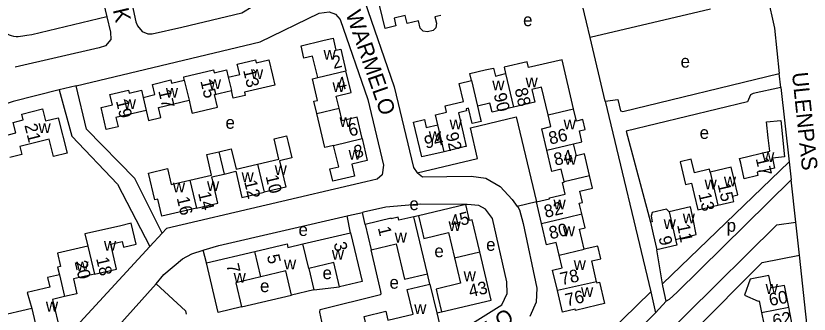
# Model space of a CAD drawing. Extents: x 157646 to 159241, y 379213 to 381217.
# Drawn here: x 158162.1 to 158413, y 380564.5 to 380658.9 of the extents above; entities that cross this region are included whole.
import ezdxf

# ---------------------------------------------------------------- set-up
doc = ezdxf.new("R2010")
doc.units = 0
for name, color, linetype in [('BLT_Basislijn', 7, 'Continuous'), ('BLT_Bebouwing', 7, 'Continuous'), ('BLT_Centroide', 7, 'Continuous'), ('BLT_Huisnummer', 7, 'Continuous'), ('BLT_Onderverdeling_panden', 7, 'Continuous'), ('BLT_Straatnaam', 7, 'Continuous')]:
    doc.layers.add(name, color=color, linetype=linetype)

msp = doc.modelspace()

# ---------------------------------------------------------------- linework, layer by layer
at = {"layer": 'BLT_Basislijn'}
for p, q in [((158348.47, 380631.87), (158343.74, 380651.99)), ((158403.98, 380636.16), (158403.54, 380640.58)), ((158181.13, 380636.75), (158175.77, 380635.43)), ((158403.98, 380636.16), (158406.62, 380612.71)), ((158348.47, 380631.87), (158362.89, 380571.52)), ((158366.63, 380574.09), (158406.62, 380612.71)), ((158406.62, 380612.71), (158407.25, 380607.02)), ((158408.77, 380593.57), (158407.25, 380607.02)), ((158326.75, 380599.99), (158320.69, 380598.56)), ((158320.69, 380598.56), (158320.81, 380598.41)), ((158267.98, 380590.24), (158266.84, 380595.55)), ((158272.54, 380592.88), (158271.76, 380596.69)), ((158289.48, 380595.61), (158288, 380595.31)), ((158409.95, 380583.17), (158408.77, 380593.57)), ((158204.53, 380585.91), (158208.41, 380590.08)), ((158222.4, 380580.73), (158221.37, 380584.71)), ((158366.63, 380574.09), (158364.79, 380584.88)), ((158293.05, 380573.96), (158292.25, 380577.28)), ((158256.33, 380572.18), (158264.49, 380573.14)), ((158366.74, 380573.46), (158366.63, 380574.09)), ((158367.81, 380568.55), (158366.74, 380573.46)), ((158233.44, 380566.78), (158249.28, 380570.51)), ((158337.01, 380546.43), (158362.89, 380571.52)), ((158362.89, 380571.52), (158364.39, 380564.93)), ((158364.39, 380564.93), (158367.81, 380568.55)), ((158295.19, 380564.9), (158296.75, 380565.24)), ((158341.49, 380542.56), (158364.39, 380564.93))]:
    msp.add_line(p, q, dxfattribs=at)
for points in [[(158190.58, 380711.16), (158188.15, 380710.58), (158188.12, 380710.02), (158194.21, 380683.94), (158200.09, 380656.96), (158200.56, 380655.7), (158202.03, 380653.89), (158203.87, 380653.16), (158205.21, 380653.16), (158214.6, 380655.3), (158233.53, 380659.84), (158237.07, 380661.95)], [(158181.94, 380696.44), (158190.9, 380658.59)], [(158334.69, 380690.66), (158334.32, 380690.56), (158306.8, 380683.88), (158298.28, 380681.17), (158288.74, 380677.5), (158275.69, 380670.09), (158272.57, 380667.25), (158272.32, 380663.58), (158281.74, 380636.45), (158287.85, 380610.84), (158289.05, 380609.24)], [(158399.81, 380664.94), (158401.98, 380654.96), (158403.54, 380640.58)], [(158190.9, 380658.59), (158192.05, 380653.74), (158192.11, 380651.39), (158190.49, 380649.39), (158188.49, 380648.79), (158161.85, 380642.64)], [(158190.9, 380658.59), (158167.11, 380652.87), (158165.54, 380652.6), (158164.27, 380652.44)], [(158181.13, 380636.75), (158239.35, 380650.66), (158258.03, 380659.68), (158261.21, 380660.16), (158263.18, 380659.36), (158264.65, 380657.71), (158273.4, 380632.41), (158278.36, 380611.6), (158277.92, 380608.61), (158276.33, 380607.24), (158272.8, 380606.31), (158209.74, 380591.54), (158208.41, 380590.08)], [(158164.27, 380652.44), (158163.58, 380652.3), (158162.87, 380652.24), (158162.17, 380652.26), (158161.47, 380652.35), (158160.78, 380652.53), (158160.12, 380652.78), (158159.49, 380653.11), (158158.91, 380653.5), (158158.43, 380653.9)], [(158348.47, 380631.87), (158352.47, 380632.4), (158353.36, 380628.8), (158354.1, 380628.64), (158403.54, 380640.58)], [(158175.77, 380635.43), (158161.21, 380631.77), (158156.75, 380630.24), (158148.79, 380625.89), (158142.68, 380620.8), (158139.58, 380617.09), (158122.17, 380593.19), (158088.91, 380548.79), (158087.38, 380546.5), (158085.15, 380541.88), (158083.98, 380537.65), (158083.7, 380528.68), (158092.89, 380456.03), (158094.64, 380453.46), (158097.98, 380452.14), (158149.23, 380463.59), (158151.12, 380464.15), (158152.81, 380465.76), (158153.39, 380468.79), (158147.46, 380517.85), (158147.9, 380522.87), (158148.44, 380524.46), (158150.49, 380527.42), (158204.53, 380585.91)], [(158175.77, 380635.43), (158179.77, 380620.83), (158194.3, 380605.62), (158204.53, 380585.91)], [(158208.41, 380590.08), (158199.74, 380607.43), (158184.4, 380622.99), (158181.13, 380636.75)], [(158403.98, 380636.16), (158395.24, 380634.32), (158394.44, 380633.84), (158393.52, 380631.63), (158355.16, 380622.42), (158362.77, 380593.59)], [(158289.05, 380609.24), (158308.12, 380613.75), (158305.84, 380623.48), (158320.32, 380626.87), (158326.75, 380599.99)], [(158289.05, 380609.24), (158289.12, 380609.15), (158290.71, 380607.93), (158306.08, 380608.13), (158310.74, 380607.49)], [(158310.74, 380607.49), (158315.24, 380604.89), (158319.09, 380600.78), (158320.69, 380598.56)], [(158407.25, 380607.02), (158371.23, 380571.45), (158368.76, 380569.11), (158367.81, 380568.55)], [(158245.14, 380520.77), (158250.62, 380526.37), (158254.8, 380529.71), (158285.96, 380548.74), (158315.78, 380567.4), (158317.48, 380571.03), (158317.34, 380574.69), (158312.89, 380594.77), (158310.67, 380597.7), (158308.56, 380598.87), (158304.79, 380599.21), (158304.38, 380599.21)], [(158304.38, 380599.21), (158290.07, 380599.3), (158279.1, 380598.35), (158272.04, 380596.75), (158271.76, 380596.69)], [(158320.81, 380598.41), (158321.35, 380597.47), (158322.52, 380593.15), (158326.84, 380572.7), (158326.63, 380568.3), (158324.66, 380563.71)], [(158221.37, 380584.71), (158221.71, 380584.82), (158226.3, 380586.21), (158266.84, 380595.55)], [(158266.84, 380595.55), (158267.29, 380595.66), (158271.76, 380596.69)], [(158345.58, 380536.24), (158402.72, 380592.79), (158408.77, 380593.57)], [(158206.48, 380574.08), (158208.92, 380577.03), (158214.82, 380582.04), (158217.71, 380583.55), (158221.37, 380584.71)], [(158245.37, 380554.46), (158246.58, 380554.68), (158259.79, 380557.7), (158258.19, 380565.13), (158258.38, 380565.93), (158277.39, 380570.67), (158277.63, 380570.93), (158277.57, 380571.67), (158274.44, 380584.86)], [(158354.88, 380525.33), (158358.68, 380528.77), (158356.65, 380540.46), (158356.75, 380541.31), (158378.2, 380545.77), (158375.99, 380558.59), (158398.1, 380580.88), (158409.95, 380583.17)], [(158382, 380486.03), (158394.7, 380478.15), (158397.65, 380476.58), (158401, 380475.76), (158402.65, 380477.1), (158414.74, 380494.85), (158416.53, 380498.98), (158417.47, 380503.76), (158417.68, 380511.48), (158409.95, 380583.17)], [(158192.44, 380460.23), (158189.56, 380457.85), (158185.09, 380454.13), (158182.48, 380452.66), (158178.96, 380452.33), (158177.37, 380452.85), (158168.77, 380457.81), (158165.12, 380461.91), (158164.05, 380463.75), (158162.83, 380467.65), (158157.4, 380511.32), (158157.32, 380517.6), (158158.75, 380521.1), (158160.25, 380523.11), (158189.19, 380554.74), (158206.48, 380574.08)], [(158206.48, 380574.08), (158215.77, 380565.54), (158215.93, 380564.47)]]:
    msp.add_lwpolyline(points, dxfattribs=at)
at = {"layer": 'BLT_Bebouwing'}
for p, q in [((158381.76, 380660.92), (158343.74, 380651.99)), ((158304.38, 380599.21), (158289.48, 380595.61)), ((158328.34, 380593.22), (158326.75, 380599.99)), ((158292.25, 380577.28), (158288, 380595.31)), ((158272.54, 380592.88), (158274.44, 380584.86)), ((158252.9, 380586.69), (158267.98, 380590.24)), ((158222.4, 380580.73), (158237.66, 380584.33)), ((158254.73, 380578.95), (158256.33, 380572.18)), ((158293.05, 380573.96), (158295.19, 380564.9)), ((158256.33, 380572.18), (158249.28, 380570.51)), ((158177.51, 380570.05), (158173.74, 380569.18))]:
    msp.add_line(p, q, dxfattribs=at)
for points in [[(158343.74, 380651.99), (158342.6, 380656.85), (158339.99, 380667.96)], [(158285.27, 380659), (158281.7, 380658.16), (158282.29, 380655.66), (158278.88, 380654.86), (158276.31, 380665.8), (158283.28, 380667.44)], [(158296.55, 380658.98), (158294.66, 380658.54), (158295.13, 380656.52), (158294.9, 380655.12), (158294.05, 380654.22), (158292.32, 380653.81), (158290.93, 380654.04), (158289.99, 380654.92), (158289.43, 380657.31), (158285.86, 380656.47), (158285.27, 380659)], [(158257.57, 380639.32), (158255.97, 380646.11), (158253.23, 380645.47), (158252.3, 380649.42), (158259.22, 380651.05), (158262.41, 380651.8), (158263.32, 380647.95), (158264.89, 380648.32), (158266.51, 380641.43)], [(158229.25, 380639.44), (158232.9, 380640.3), (158232.13, 380643.6), (158237.93, 380644.97), (158238.15, 380644.01), (158242.1, 380644.94), (158243.24, 380640.08), (158243.97, 380636.98), (158234.37, 380634.72), (158234.62, 380633.65), (158230.88, 380632.77), (158230.29, 380635.27)], [(158338.49, 380629.41), (158334.83, 380644.99), (158324.26, 380642.51), (158323.84, 380644.3), (158316.5, 380642.58), (158316.97, 380640.57)], [(158215.36, 380638.55), (158215.22, 380639.54), (158224.61, 380641.75), (158224.82, 380640.83), (158228.71, 380641.75), (158229.25, 380639.44)], [(158264.34, 380629.61), (158263.43, 380633.48), (158268.13, 380634.59), (158266.51, 380641.43)], [(158306.19, 380638.36), (158305.67, 380640.59), (158310.54, 380641.73), (158313.2, 380642.36), (158313.8, 380639.83), (158316.97, 380640.57)], [(158202.38, 380633.06), (158206.07, 380633.93), (158205.3, 380637.19), (158211.14, 380638.57), (158211.37, 380637.61), (158215.36, 380638.55)], [(158257.31, 380627.95), (158256.38, 380631.87), (158257.48, 380632.13), (158255.87, 380638.95), (158257.57, 380639.32)], [(158295.58, 380624.39), (158294.83, 380627.59), (158298.32, 380628.41), (158297.85, 380630.4), (158303.66, 380631.76), (158302.32, 380637.45), (158306.19, 380638.36)], [(158203.35, 380628.95), (158193.76, 380626.69), (158194.45, 380623.78), (158190.72, 380622.9), (158189.07, 380629.88), (158192.64, 380630.72), (158191.88, 380633.95), (158197.74, 380635.33), (158197.96, 380634.38), (158201.85, 380635.3), (158202.38, 380633.06)], [(158330.43, 380627.56), (158328.37, 380636.31), (158325.27, 380635.58), (158326.21, 380631.54), (158319.46, 380629.95)], [(158216.88, 380632.15), (158217.47, 380629.64), (158217.85, 380628.03), (158225.88, 380629.93), (158224.92, 380634.01)], [(158224.92, 380634.01), (158230.29, 380635.27)], [(158203.35, 380628.95), (158204.09, 380625.8), (158207.96, 380626.71), (158207.21, 380629.87), (158216.88, 380632.15)], [(158308.08, 380630.33), (158308.98, 380626.59), (158309.26, 380625.42), (158306.43, 380624.76), (158305.28, 380629.68), (158304.5, 380629.49), (158304.66, 380628.82), (158302.05, 380628.21), (158303.58, 380621.71), (158304.56, 380617.54), (158304.29, 380617.48), (158297.52, 380615.89)], [(158319.46, 380629.95), (158312.72, 380628.36), (158312.04, 380631.26), (158308.08, 380630.33)], [(158158.51, 380620.92), (158162.07, 380621.82), (158161.24, 380625.12), (158164.43, 380625.92), (158163.97, 380627.78), (158170.56, 380629.43), (158171.52, 380625.6), (158175.5, 380626.6), (158178.31, 380615.45), (158173.99, 380614.37), (158172.61, 380619.86), (158163.4, 380617.54), (158164.03, 380615.02), (158160.23, 380614.07)], [(158262.61, 380617.89), (158259.85, 380617.17), (158257.31, 380627.95)], [(158271.6, 380620.01), (158270.01, 380626.8), (158265.27, 380625.68), (158264.34, 380629.61)], [(158338.46, 380618.36), (158341.13, 380618.99), (158340.32, 380622.45), (158342.19, 380622.89), (158341.44, 380626.06), (158339.39, 380625.58), (158338.49, 380629.41)], [(158297.52, 380615.89), (158290.48, 380614.23), (158287.88, 380625.24), (158291.33, 380626.05), (158291.92, 380623.53), (158295.58, 380624.39)], [(158330.03, 380616.38), (158328.44, 380623.14), (158331.31, 380623.81), (158330.43, 380627.56)], [(158400.07, 380620.32), (158399.54, 380625.3), (158404.01, 380625.77), (158405.23, 380614.21), (158401.38, 380613.8), (158401.99, 380610.68), (158396.57, 380609.38), (158396.8, 380608.39), (158392.46, 380607.35), (158391.33, 380612.21), (158390.97, 380613.73), (158400.52, 380616.02), (158400.07, 380620.32)], [(158238.53, 380611.91), (158245.32, 380613.51), (158243.81, 380619.94), (158247.74, 380620.86), (158248.23, 380618.79), (158249.38, 380613.92), (158245.49, 380613.01), (158247.45, 380604.69), (158240.61, 380603.08)], [(158271.6, 380620.01), (158273.24, 380613.09), (158268.36, 380611.94), (158269.25, 380608.15), (158262.37, 380606.53), (158261.45, 380610.45), (158264.21, 380611.11), (158262.61, 380617.89)], [(158343.56, 380608.34), (158341.96, 380615.17), (158339.36, 380614.56), (158338.46, 380618.36)], [(158217.12, 380606.88), (158224, 380608.5), (158222.47, 380614.98), (158226.34, 380615.89)], [(158226.34, 380615.89), (158230.21, 380616.81), (158231.74, 380610.31), (158238.53, 380611.91)], [(158335.47, 380606.44), (158334.56, 380610.32), (158331.62, 380609.63), (158330.03, 380616.38)], [(158381.65, 380609.44), (158381.45, 380610.34), (158376.73, 380609.23), (158375.72, 380613.52), (158372.21, 380612.69), (158373.91, 380605.54), (158375.78, 380605.97)], [(158219.21, 380598.02), (158208.29, 380595.45), (158207.01, 380600.91), (158206.03, 380600.68), (158204.05, 380609.12), (158210.03, 380610.53), (158211.22, 380605.49)], [(158384.09, 380598.96), (158389.12, 380600.13), (158388.72, 380601.87), (158390.38, 380602.25), (158389.24, 380607.12), (158388.35, 380610.99), (158381.65, 380609.44)], [(158219.21, 380598.02), (158226.01, 380599.62), (158224.06, 380607.89), (158228.01, 380608.82)], [(158228.01, 380608.82), (158231.65, 380609.68), (158233.59, 380601.43), (158240.61, 380603.08)], [(158341.08, 380596.22), (158340.29, 380599.56), (158341.29, 380599.8), (158340.45, 380603.36), (158344.51, 380604.32), (158343.56, 380608.34)], [(158211.22, 380605.49), (158217.12, 380606.88)], [(158335.81, 380602.42), (158334.94, 380606.09), (158335.52, 380606.22), (158335.47, 380606.44)], [(158375.78, 380605.97), (158376.62, 380602.36), (158377.75, 380597.49), (158384.09, 380598.96)], [(158326.75, 380599.99), (158330.9, 380600.96), (158330.83, 380601.25), (158335.81, 380602.42)], [(158308.81, 380584.16), (158306.42, 380594.33), (158305.56, 380594.13), (158304.38, 380599.21)], [(158368.73, 380596.82), (158367.91, 380597.72), (158363.32, 380596.65), (158362.98, 380595.51), (158363.39, 380593.74), (158362.77, 380593.59)], [(158370.74, 380588.16), (158377.29, 380589.68), (158376.29, 380594.58), (158375.51, 380598.4), (158368.73, 380596.82)], [(158288, 380595.31), (158283.25, 380594.19), (158283.02, 380595.2), (158280.82, 380594.68), (158280.78, 380594.82), (158272.54, 380592.88)], [(158289.48, 380595.61), (158290.62, 380590.74), (158291.17, 380588.45), (158298.97, 380590.29), (158300.86, 380582.28)], [(158341.84, 380585.01), (158340.36, 380591.33), (158342.13, 380591.75), (158341.08, 380596.22)], [(158187.02, 380577.16), (158193.93, 380578.75), (158192.11, 380586.68), (158195.71, 380587.51), (158196.12, 380585.7), (158200.12, 380586.61), (158198.59, 380593.24), (158194.85, 380592.38), (158183.97, 380589.88), (158184.87, 380585.95)], [(158333.88, 380583.14), (158332.94, 380587.17), (158329.92, 380586.46), (158328.34, 380593.22)], [(158362.77, 380593.59), (158363.66, 380589.76), (158364.79, 380584.88)], [(158267.98, 380590.24), (158271.62, 380574.82), (158264.49, 380573.14)], [(158370.74, 380588.16), (158371.16, 380586.36), (158364.79, 380584.88)], [(158184.87, 380585.95), (158175.31, 380583.75), (158176.27, 380579.57), (158175.33, 380579.35), (158175.92, 380576.97)], [(158237.66, 380584.33), (158247.87, 380586.74), (158248.15, 380585.57), (158252.9, 380586.69)], [(158274.44, 380584.86), (158282.38, 380586.73), (158285.01, 380575.57), (158292.25, 380577.28)], [(158345.77, 380574.68), (158344.21, 380581.33), (158347.12, 380582.01), (158346.19, 380585.97), (158341.84, 380585.01)], [(158296.75, 380565.24), (158312.39, 380568.94), (158308.81, 380584.16)], [(158333.39, 380571.97), (158331.87, 380578.43), (158334.83, 380579.12), (158333.88, 380583.14)], [(158233.44, 380566.78), (158226.1, 380565.04), (158222.4, 380580.73)], [(158264.49, 380573.14), (158262.67, 380580.83), (158254.73, 380578.95)], [(158300.86, 380582.28), (158302.75, 380574.27), (158295.04, 380572.45), (158295.6, 380570.11), (158296.75, 380565.24)], [(158249.28, 380570.51), (158247.47, 380578.17), (158239.55, 380576.3)], [(158175.92, 380576.97), (158172.15, 380576.1), (158172.87, 380573)], [(158187.02, 380577.16), (158180.32, 380575.62), (158181.39, 380570.94), (158177.51, 380570.05)], [(158239.55, 380576.3), (158231.63, 380574.43), (158233.44, 380566.78)], [(158406.56, 380566.72), (158405.24, 380573.58), (158401.05, 380572.77), (158400.28, 380576.75), (158394.34, 380575.61), (158392.55, 380570.48), (158396.86, 380568.64), (158397.2, 380568.71), (158397.91, 380565.06)], [(158172.87, 380573), (158165.71, 380571.36), (158167.16, 380566.23)], [(158279.73, 380562.58), (158287.75, 380564.47), (158285.91, 380572.27), (158293.05, 380573.96)], [(158345.77, 380574.68), (158345.84, 380574.39), (158346.68, 380574.59), (158348.26, 380567.85), (158346.04, 380567.33), (158339.11, 380565.7), (158339.02, 380566.08), (158334.99, 380565.14), (158333.39, 380571.97)], [(158173.74, 380569.18), (158176.09, 380558.98), (158169.19, 380557.39)], [(158167.16, 380566.23), (158156.24, 380563.72), (158157.58, 380557.89)], [(158266.08, 380554.12), (158274.05, 380556), (158272.21, 380563.77), (158279.07, 380565.39), (158279.73, 380562.58)], [(158397.91, 380565.06), (158398.61, 380561.41), (158394.14, 380560.55), (158395.09, 380555.64), (158395.5, 380553.5)], [(158403.65, 380555.07), (158402.88, 380559.08), (158407.85, 380560.04), (158406.56, 380566.72)], [(158295.19, 380564.9), (158296.47, 380559.49), (158291.75, 380558.38), (158292.03, 380557.2), (158281.8, 380554.78)]]:
    msp.add_lwpolyline(points, dxfattribs=at)
at = {"layer": 'BLT_Onderverdeling_panden'}
for p, q in [((158257.57, 380639.32), (158266.51, 380641.43)), ((158316.97, 380640.57), (158319.46, 380629.95)), ((158215.36, 380638.55), (158216.88, 380632.15)), ((158229.25, 380639.44), (158230.29, 380635.27)), ((158306.19, 380638.36), (158308.08, 380630.33)), ((158202.38, 380633.06), (158203.35, 380628.95)), ((158257.31, 380627.95), (158264.34, 380629.61)), ((158330.43, 380627.56), (158338.49, 380629.41)), ((158297.52, 380615.89), (158295.58, 380624.39)), ((158262.61, 380617.89), (158271.6, 380620.01)), ((158330.03, 380616.38), (158338.46, 380618.36)), ((158226.34, 380615.89), (158228.01, 380608.82)), ((158238.53, 380611.91), (158240.61, 380603.08)), ((158335.47, 380606.44), (158343.56, 380608.34)), ((158381.65, 380609.44), (158384.09, 380598.96)), ((158217.12, 380606.88), (158219.21, 380598.02)), ((158328.34, 380593.22), (158336.73, 380595.19)), ((158336.73, 380595.19), (158341.08, 380596.22)), ((158368.73, 380596.82), (158370.74, 380588.16)), ((158184.87, 380585.95), (158187.02, 380577.16)), ((158254.73, 380578.95), (158252.9, 380586.69)), ((158239.55, 380576.3), (158237.66, 380584.33)), ((158300.86, 380582.28), (158308.81, 380584.16)), ((158333.88, 380583.14), (158341.84, 380585.01)), ((158175.92, 380576.97), (158177.51, 380570.05)), ((158345.77, 380574.68), (158333.39, 380571.97)), ((158167.16, 380566.23), (158169.19, 380557.39)), ((158397.91, 380565.06), (158406.56, 380566.72))]:
    msp.add_line(p, q, dxfattribs=at)

# ---------------------------------------------------------------- texts
at = {"layer": 'BLT_Centroide'}
for s, p in [('e', (158322.52, 380655.6)), ('w', (158259.41, 380645)), ('e', (158372.33, 380642.49)), ('w', (158236.46, 380638.88)), ('w', (158223.13, 380635.69)), ('w', (158262.25, 380634.78)), ('w', (158312.77, 380635.31)), ('w', (158323.3, 380636.28)), ('w', (158209.54, 380633)), ('w', (158196.23, 380629.34)), ('e', (158228.41, 380623.14)), ('w', (158264.45, 380623.73)), ('w', (158299.27, 380622.99)), ('w', (158335.34, 380622.91)), ('w', (158169.27, 380621.75)), ('e', (158378.35, 380619.93)), ('w', (158292.7, 380619.23)), ('w', (158267.34, 380613.34)), ('w', (158398.09, 380612.59)), ('w', (158335.62, 380611.73)), ('w', (158243.95, 380608.53)), ('w', (158233.48, 380606.31)), ('w', (158386.02, 380604.92)), ('w', (158211.76, 380603)), ('w', (158222.56, 380603.48)), ('w', (158379.91, 380603.98)), ('e', (158286.57, 380597.41)), ('w', (158332.14, 380597.6)), ('w', (158373, 380593.25)), ('w', (158298.95, 380590.75)), ('w', (158366.97, 380591.44)), ('p', (158386.89, 380590.56)), ('e', (158251.5, 380589.22)), ('w', (158281.91, 380587.16)), ('w', (158335.07, 380589.16)), ('e', (158310.83, 380584.54)), ('w', (158189.97, 380584.55)), ('e', (158294.47, 380582.49)), ('w', (158262.04, 380581.69)), ('w', (158181.23, 380578)), ('w', (158246.9, 380578.62)), ('w', (158338.52, 380578.5)), ('e', (158259.1, 380575.55)), ('w', (158303.72, 380574.92)), ('w', (158230.97, 380574.47)), ('e', (158280.27, 380572.55)), ('e', (158239.33, 380571.46)), ('w', (158340.83, 380569.91)), ('w', (158399.23, 380570.91)), ('w', (158171.61, 380565.33)), ('w', (158288.09, 380564.53))]:
    msp.add_text(s, height=4, dxfattribs=at).set_placement(p)
at = {"layer": 'BLT_Huisnummer'}
for s, rotation, p in [('2', 13.2613, (158262.63, 380642.05)), ('13', 283.256, (158233.95, 380641.67)), ('15', 283.2651, (158220.43, 380638.27)), ('4', 13.2613, (158264.19, 380635.18)), ('17', 283.264, (158207.13, 380635.12)), ('88', 283.2193, (158319.82, 380635.65)), ('90', 283.224, (158313.18, 380634.03)), ('19', 283.2613, (158193.73, 380631.97)), ('21', 284.1097, (158164.78, 380624.26)), ('6', 13.2613, (158267.77, 380620.64)), ('86', 13.2283, (158331.1, 380618.11)), ('94', 13.2875, (158291.77, 380616.8)), ('92', 283.2243, (158297.98, 380621.57)), ('8', 13.2613, (158269.5, 380613.76)), ('84', 13.2143, (158332.73, 380611.4)), ('17', 283.1552, (158396.05, 380613.72)), ('10', 283.262, (158241.07, 380608.11)), ('12', 283.261, (158234.27, 380606.47)), ('15', 283.0831, (158383.99, 380605.58)), ('14', 283.2602, (158219.71, 380602.8)), ('13', 283.0831, (158377.94, 380602.53)), ('16', 283.2666, (158212.94, 380601.24)), ('82', 13.2182, (158329.66, 380594.92)), ('45', 13.2838, (158300.03, 380591.77)), ('80', 13.2297, (158331.2, 380588.15)), ('11', 281.5009, (158371.2, 380592.7)), ('1', 283.2823, (158276.55, 380591.81)), ('9', 283.0831, (158365.32, 380588.76)), ('3', 283.2816, (158262.56, 380586.91)), ('5', 283.286, (158241.45, 380582.96)), ('20', 282.9454, (158180.67, 380581.04)), ('18', 282.9404, (158187.46, 380582.11)), ('7', 283.2839, (158228.62, 380580.03)), ('78', 13.2053, (158334.74, 380573.59)), ('43', 13.2858, (158305.8, 380569.79)), ('76', 13.2254, (158336.35, 380566.93)), ('60', 10.8928, (158400.64, 380567.02)), ('62', 10.8928, (158401.8, 380560.36))]:
    msp.add_text(s, height=4, rotation=rotation, dxfattribs=at).set_placement(p)
at = {"layer": 'BLT_Straatnaam'}
for s, rotation, p in [('ROOSWIJCK', 283.1446, (158184.55, 380695.84)), ('WARMELO', 289.08, (158266.33, 380659.6)), ('ULENPAS', 275.9474, (158407.55, 380640.82)), ('WARMELO', 32.6243, (158290.96, 380543.78))]:
    msp.add_text(s, height=5, rotation=rotation, dxfattribs=at).set_placement(p)

doc.saveas('drawing.dxf')
